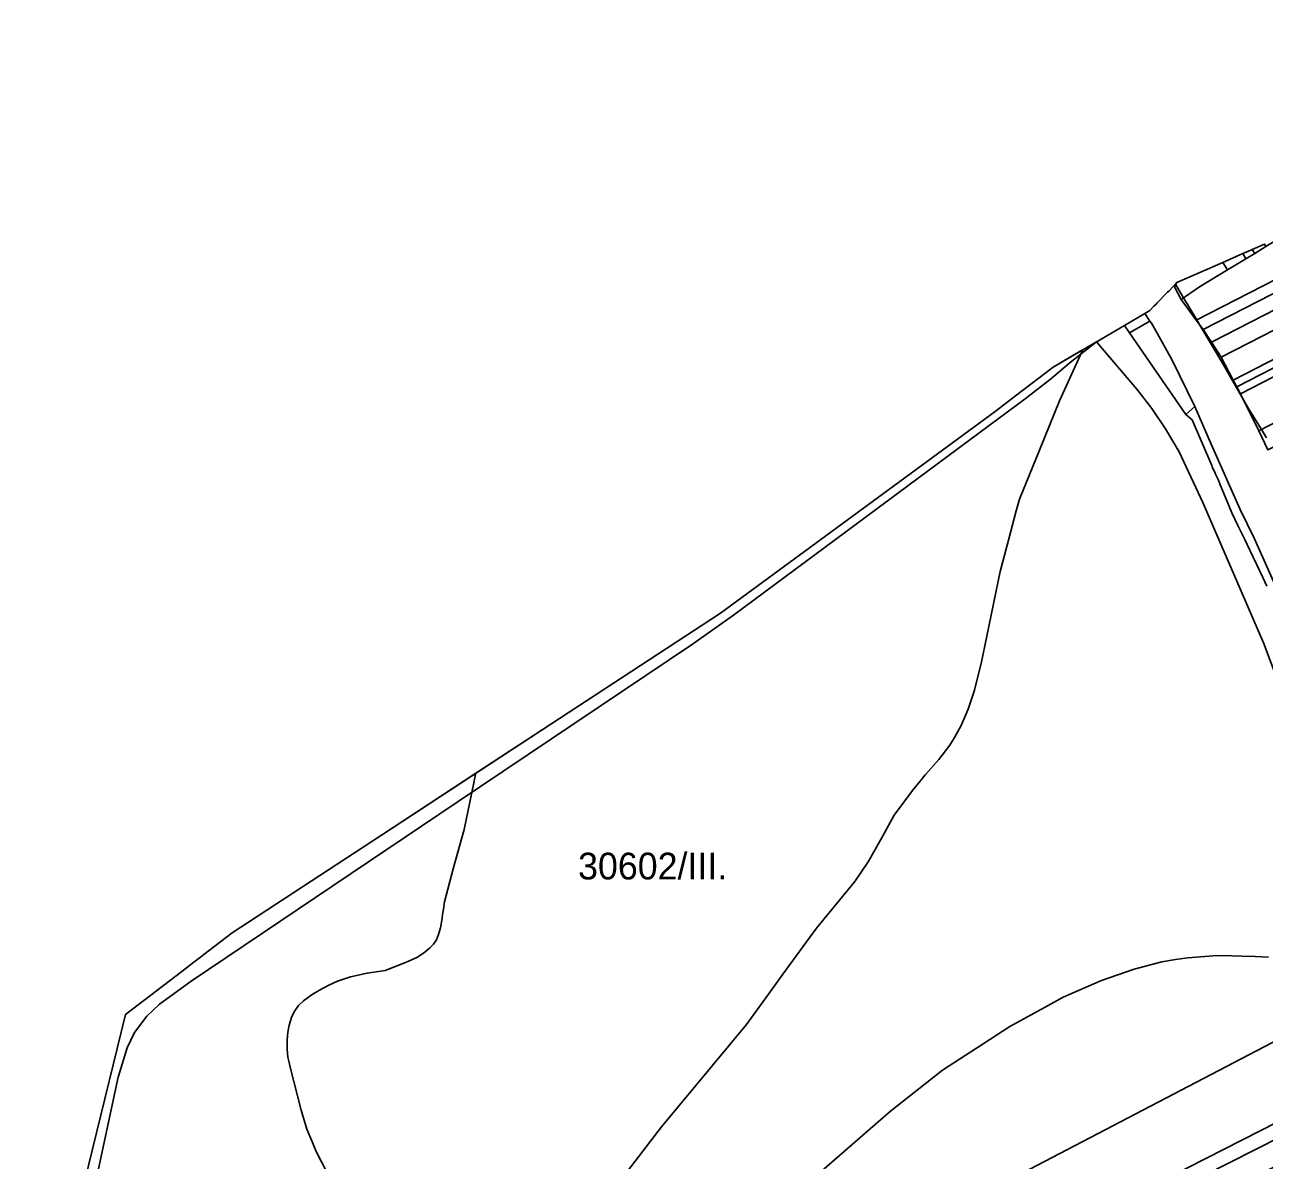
# Model space of a CAD drawing. Extents: x -521939 to -516426, y -1197857 to -1189551.
# Drawn here: x -521520 to -520825, y -1190213 to -1189576 of the extents above; entities that cross this region are included whole.
import ezdxf

# ---------------------------------------------------------------- set-up
doc = ezdxf.new("R2010")
doc.units = 0
for name, color, linetype in [('95560013', 7, 'Continuous'), ('95640013', 7, 'Continuous'), ('95660013', 7, 'Continuous')]:
    doc.layers.add(name, color=color, linetype=linetype)

msp = doc.modelspace()

# ---------------------------------------------------------------- linework, layer by layer
at = {"layer": '95560013'}
for points in [[(-520871.46, -1189729.85), (-520861.25, -1189722.78), (-520845.5, -1189713.21), (-520835.28, -1189707), (-520830.24, -1189703.94), (-520823.89, -1189700.08), (-520813.62, -1189693.84), (-520798.15, -1189685.87), (-520693.52, -1189631.98), (-520584.33, -1189575.74), (-520574.91, -1189593.69), (-520698.86, -1189657.27), (-520862.97, -1189741.45)], [(-520574.91, -1189593.69), (-520571.87, -1189599.49), (-520698.91, -1189664.62), (-520859.09, -1189746.74), (-520862.97, -1189741.45), (-520698.86, -1189657.27)], [(-520571.87, -1189599.49), (-520567.98, -1189606.88), (-520692.96, -1189670.96), (-520854.49, -1189753.78), (-520859.09, -1189746.74), (-520698.91, -1189664.62)], [(-520567.98, -1189606.88), (-520563.29, -1189615.69), (-520689.07, -1189680.22), (-520848.98, -1189762.26), (-520854.49, -1189753.78), (-520692.96, -1189670.96)], [(-520563.29, -1189615.69), (-520556.78, -1189628.12), (-520695.46, -1189699.52), (-520842.22, -1189775.08), (-520848.98, -1189762.26), (-520689.07, -1189680.22)], [(-520556.78, -1189628.12), (-520554.77, -1189631.94), (-520679.88, -1189696.34), (-520840.25, -1189778.89), (-520842.22, -1189775.08), (-520695.46, -1189699.52)], [(-520554.77, -1189631.94), (-520552.78, -1189635.77), (-520677.43, -1189699.92), (-520838.28, -1189782.7), (-520840.25, -1189778.89), (-520679.88, -1189696.34)], [(-520552.78, -1189635.77), (-520542.06, -1189656.2), (-520665.51, -1189719.78), (-520827.89, -1189803.41), (-520838.28, -1189782.7), (-520677.43, -1189699.92)], [(-520542.06, -1189656.2), (-520536.5, -1189666.75), (-520663.27, -1189732.03), (-520822.82, -1189814.19), (-520827.89, -1189803.41), (-520665.51, -1189719.78)], [(-520830.24, -1189703.94), (-520831.59, -1189701.76), (-520824.7, -1189698.73), (-520823.89, -1189700.08)], [(-520845.5, -1189713.21), (-520848.1, -1189709.03), (-520836.95, -1189704.12), (-520835.28, -1189707)], [(-520835.28, -1189707), (-520836.95, -1189704.12), (-520832.44, -1189702.13), (-520831.59, -1189701.76), (-520830.24, -1189703.94)], [(-520891.87, -1189737.62), (-520889, -1189741.91), (-520900.54, -1189748.5), (-520903.31, -1189744.33)], [(-520888.2, -1189743.1), (-520884.99, -1189748.66), (-520876.58, -1189763.88), (-520863.78, -1189789.93), (-520868.84, -1189794.27), (-520900.54, -1189748.5), (-520889, -1189741.91)], [(-521143.74, -1190315.4), (-520777.95, -1190124.57), (-520777.29, -1190138.74), (-520776.47, -1190163.36), (-520776.83, -1190170.44), (-521129.32, -1190350.03), (-521136.18, -1190333.63), (-521138.91, -1190327.09), (-521141.12, -1190321.7)], [(-521125.92, -1190356.73), (-521201.05, -1190394.9), (-521360.62, -1190475.97), (-521520.19, -1190557.04), (-521519.05, -1190548.23), (-521358.95, -1190466.81), (-521197.1, -1190384.5), (-521129.32, -1190350.03), (-520776.83, -1190170.44), (-520777.49, -1190180.07), (-520800.29, -1190191.63), (-520962.75, -1190274)], [(-521125.92, -1190356.73), (-520962.75, -1190274), (-520800.29, -1190191.63), (-520777.49, -1190180.07), (-520778.53, -1190195.44), (-520799.56, -1190206.22), (-520959.86, -1190288.39), (-521120.16, -1190370.56), (-521122.27, -1190365.51)]]:
    msp.add_lwpolyline(points, close=True, dxfattribs=at)
for points in [[(-521480.04, -1190222.68), (-521467.81, -1190165.95), (-521462.67, -1190149.67), (-521458.62, -1190141.01), (-521451.74, -1190131.75), (-521444.63, -1190125.14), (-521426.94, -1190112.16), (-521277.58, -1190011.81), (-521145.53, -1189923.09), (-521122.58, -1189906.88), (-520979.19, -1189800.51), (-520959.01, -1189785.54), (-520944.79, -1189774.51), (-520933.78, -1189765.22), (-520918.93, -1189753.5), (-520896.35, -1189780.16), (-520887.88, -1189790.95), (-520880.21, -1189802.32), (-520872.55, -1189815.19), (-520859.28, -1189843.65), (-520825.3, -1189922.44), (-520803.36, -1189980.65)], [(-520777.95, -1190124.57), (-521143.74, -1190315.4)]]:
    msp.add_lwpolyline(points, dxfattribs=at)
at = {"layer": '95640013'}
msp.add_lwpolyline([(-520875.18, -1189722.65), (-520873.85, -1189720.38), (-520848.1, -1189709.03), (-520845.5, -1189713.21), (-520861.25, -1189722.78), (-520871.46, -1189729.85)], close=True, dxfattribs=at)
for points in [[(-520813.42, -1189901.77), (-520830.43, -1189864.05), (-520838.34, -1189847.6), (-520854.68, -1189811.01), (-520863.78, -1189789.93), (-520876.58, -1189763.88), (-520884.99, -1189748.66), (-520888.2, -1189743.1), (-520889, -1189741.91), (-520891.87, -1189737.62), (-520889.06, -1189735.97), (-520886.75, -1189733.61), (-520885.77, -1189732.6), (-520884.86, -1189731.67), (-520879.1, -1189725.76), (-520878.47, -1189725.11), (-520878.3, -1189724.93), (-520873.85, -1189720.38), (-520875.18, -1189722.65), (-520871.46, -1189729.85), (-520862.97, -1189741.45), (-520859.09, -1189746.74), (-520854.49, -1189753.78), (-520848.98, -1189762.26), (-520842.22, -1189775.08), (-520840.25, -1189778.89), (-520838.28, -1189782.7), (-520827.89, -1189803.41), (-520822.82, -1189814.19)], [(-520803.36, -1189980.65), (-520825.3, -1189922.44), (-520859.28, -1189843.65), (-520872.55, -1189815.19), (-520880.21, -1189802.32), (-520887.88, -1189790.95), (-520896.35, -1189780.16), (-520918.93, -1189753.5), (-520918.65, -1189753.34), (-520903.31, -1189744.33), (-520900.54, -1189748.5), (-520868.84, -1189794.27), (-520865.38, -1189797.27), (-520854.32, -1189823.02), (-520854.03, -1189823.64), (-520852.36, -1189827.29), (-520852.17, -1189827.72), (-520850.55, -1189831.25), (-520849.51, -1189833.76), (-520846.54, -1189840.93), (-520843.01, -1189849.46), (-520839.61, -1189856.58), (-520835.85, -1189864.43), (-520832.97, -1189870.44), (-520829.04, -1189878.62), (-520825.65, -1189885.69), (-520823.49, -1189890.54)], [(-521489.18, -1190234.62), (-521463.67, -1190130.83), (-521432.08, -1190106.71), (-521425.29, -1190101.52), (-521421.67, -1190098.76), (-521419.72, -1190097.27), (-521403.82, -1190085.13), (-521320.06, -1190030.25), (-521225, -1189967.98), (-521129.95, -1189905.7), (-520975.8, -1189792.72), (-520964.34, -1189783.94), (-520943.19, -1189767.73), (-520918.93, -1189753.5), (-520933.78, -1189765.22), (-520944.79, -1189774.51), (-520959.01, -1189785.54), (-520979.19, -1189800.51), (-521122.58, -1189906.88), (-521145.53, -1189923.09), (-521277.58, -1190011.81), (-521426.94, -1190112.16), (-521444.63, -1190125.14), (-521451.74, -1190131.75), (-521458.62, -1190141.01), (-521462.67, -1190149.67), (-521467.81, -1190165.95), (-521480.04, -1190222.68)], [(-520823.49, -1189890.54), (-520825.65, -1189885.69), (-520829.04, -1189878.62), (-520832.97, -1189870.44), (-520835.85, -1189864.43), (-520839.61, -1189856.58), (-520843.01, -1189849.46), (-520846.54, -1189840.93), (-520849.51, -1189833.76), (-520850.55, -1189831.25), (-520852.17, -1189827.72), (-520852.36, -1189827.29), (-520854.03, -1189823.64), (-520854.32, -1189823.02), (-520865.38, -1189797.27), (-520868.84, -1189794.27), (-520863.78, -1189789.93), (-520854.68, -1189811.01), (-520838.34, -1189847.6), (-520830.43, -1189864.05), (-520813.42, -1189901.77)]]:
    msp.add_lwpolyline(points, dxfattribs=at)
at = {"layer": '95660013'}
for points in [[(-520823.56, -1189807.36), (-520826.49, -1189802.69), (-520830.43, -1189796.42), (-520833.59, -1189791.38), (-520836.57, -1189786.11), (-520847.7, -1189766.42), (-520860.96, -1189744.19), (-520862.68, -1189741.3), (-520870.08, -1189728.9), (-520873.84, -1189722.6), (-520874.5, -1189721.5), (-520874.67, -1189721.22), (-520873.85, -1189720.38), (-520848.1, -1189709.03), (-520836.95, -1189704.12), (-520832.44, -1189702.13), (-520831.59, -1189701.76), (-520824.7, -1189698.73)], [(-521239.8, -1190294.2), (-521163.05, -1190193.89), (-521115.23, -1190136.51), (-521100.61, -1190116.17), (-521094.94, -1190108.28), (-521076.04, -1190082.38), (-521054.58, -1190056.26), (-521047.11, -1190045.29), (-521039.88, -1190032.7), (-521032.42, -1190019.17), (-521022.15, -1190005.17), (-521017.91, -1190000), (-521015.05, -1189996.51), (-521014.69, -1189996.07), (-521007.46, -1189987.91), (-521001.16, -1189979.74), (-520998.64, -1189975.56), (-520994.9, -1189968.79), (-520993.2, -1189964.89), (-520990.94, -1189959.69), (-520987.44, -1189948.96), (-520983.47, -1189933.1), (-520981.64, -1189924.13), (-520973.09, -1189882.36), (-520968.43, -1189864.87), (-520964.11, -1189848.42), (-520962.24, -1189841.77), (-520950.93, -1189814.36), (-520939.73, -1189786.72), (-520928.11, -1189761.16), (-520927.82, -1189760.51), (-520926.7, -1189758.06), (-520928.1, -1189758.88), (-520943.19, -1189767.73), (-520918.93, -1189753.5), (-520918.65, -1189753.34), (-520903.31, -1189744.33), (-520891.87, -1189737.62), (-520889.06, -1189735.97), (-520886.75, -1189733.61), (-520885.77, -1189732.6), (-520884.86, -1189731.67), (-520879.1, -1189725.76), (-520878.47, -1189725.11), (-520878.3, -1189724.93), (-520873.85, -1189720.38), (-520874.67, -1189721.22), (-520874.5, -1189721.5), (-520873.84, -1189722.6), (-520870.08, -1189728.9), (-520862.68, -1189741.3), (-520860.96, -1189744.19), (-520847.7, -1189766.42), (-520836.57, -1189786.11), (-520833.59, -1189791.38), (-520830.43, -1189796.42), (-520826.49, -1189802.69), (-520823.56, -1189807.36)], [(-521350.73, -1190219.4), (-521356.72, -1190207.83), (-521358.88, -1190202.7), (-521362.05, -1190195.16), (-521365.17, -1190184.51), (-521371.25, -1190160.35), (-521372.06, -1190157.09), (-521372.61, -1190154.86), (-521373.03, -1190150.55), (-521372.94, -1190145.14), (-521372.79, -1190143.1), (-521372.61, -1190140.75), (-521371.85, -1190136.78), (-521370.58, -1190132.56), (-521369.14, -1190129.35), (-521366.61, -1190125.8), (-521363.82, -1190123.18), (-521359, -1190119.72), (-521354.95, -1190117.18), (-521349.54, -1190114.48), (-521344.81, -1190112.28), (-521337.55, -1190109.75), (-521328.09, -1190107.72), (-521317.95, -1190106.2), (-521307.47, -1190102.15), (-521304.02, -1190100.62), (-521300.21, -1190098.93), (-521296.49, -1190096.57), (-521293.11, -1190093.7), (-521290.91, -1190091.5), (-521289.22, -1190088.97), (-521288.04, -1190085.93), (-521287.03, -1190082.21), (-521286.18, -1190077.98), (-521285.59, -1190073.59), (-521285.34, -1190071.73), (-521284.83, -1190067.68), (-521279.93, -1190049.09), (-521273.68, -1190027.13), (-521269.37, -1190006.3), (-521268.07, -1190000), (-521267.85, -1189998.95), (-521267.16, -1189995.6), (-521225, -1189967.98), (-521129.95, -1189905.7), (-520975.8, -1189792.72), (-520964.34, -1189783.94), (-520943.19, -1189767.73), (-520928.1, -1189758.88), (-520926.7, -1189758.06), (-520927.82, -1189760.51), (-520928.11, -1189761.16), (-520939.73, -1189786.72), (-520950.93, -1189814.36), (-520962.24, -1189841.77), (-520964.11, -1189848.42), (-520968.43, -1189864.87), (-520973.09, -1189882.36), (-520981.64, -1189924.13), (-520983.47, -1189933.1), (-520987.44, -1189948.96), (-520990.94, -1189959.69), (-520993.2, -1189964.89), (-520994.9, -1189968.79), (-520998.64, -1189975.56), (-521001.16, -1189979.74), (-521007.46, -1189987.91), (-521014.69, -1189996.07), (-521015.05, -1189996.51), (-521017.91, -1190000), (-521022.15, -1190005.17), (-521032.42, -1190019.17), (-521039.88, -1190032.7), (-521047.11, -1190045.29), (-521054.58, -1190056.26), (-521076.04, -1190082.38), (-521094.94, -1190108.28), (-521100.61, -1190116.17), (-521115.23, -1190136.51), (-521163.05, -1190193.89), (-521239.8, -1190294.2)], [(-521320.06, -1190030.25), (-521267.16, -1189995.6), (-521267.85, -1189998.95), (-521268.07, -1190000), (-521269.37, -1190006.3), (-521273.68, -1190027.13), (-521279.93, -1190049.09), (-521284.83, -1190067.68), (-521285.34, -1190071.73), (-521285.59, -1190073.59), (-521286.18, -1190077.98), (-521287.03, -1190082.21), (-521288.04, -1190085.93), (-521289.22, -1190088.97), (-521290.91, -1190091.5), (-521293.11, -1190093.7), (-521296.49, -1190096.57), (-521300.21, -1190098.93), (-521304.02, -1190100.62), (-521307.47, -1190102.15), (-521317.95, -1190106.2), (-521328.09, -1190107.72), (-521337.55, -1190109.75), (-521344.81, -1190112.28), (-521349.54, -1190114.48), (-521354.95, -1190117.18), (-521359, -1190119.72), (-521363.82, -1190123.18), (-521366.61, -1190125.8), (-521369.14, -1190129.35), (-521370.58, -1190132.56), (-521371.85, -1190136.78), (-521372.61, -1190140.75), (-521372.79, -1190143.1), (-521372.94, -1190145.14), (-521373.03, -1190150.55), (-521372.61, -1190154.86), (-521372.06, -1190157.09), (-521371.25, -1190160.35), (-521365.17, -1190184.51), (-521362.05, -1190195.16), (-521358.88, -1190202.7), (-521356.72, -1190207.83), (-521350.73, -1190219.4)], [(-521489.18, -1190234.62), (-521463.67, -1190130.83), (-521432.08, -1190106.71), (-521425.29, -1190101.52), (-521421.67, -1190098.76), (-521419.72, -1190097.27), (-521403.82, -1190085.13), (-521320.06, -1190030.25)], [(-520822.42, -1190098.78), (-520830.02, -1190098.43), (-520837.45, -1190098.08), (-520842.92, -1190097.98), (-520851.06, -1190097.84), (-520867.73, -1190099.02), (-520874.6, -1190100.12), (-520882.28, -1190101.36), (-520897.84, -1190105.47), (-520916.15, -1190111.81), (-520937.74, -1190121.2), (-520946.16, -1190125.84), (-520967.56, -1190137.63), (-520986.33, -1190149.76), (-521005.35, -1190162.05), (-521034.46, -1190185.05), (-521063.1, -1190209.93), (-521088.69, -1190232.24)], [(-521088.69, -1190232.24), (-521063.1, -1190209.93), (-521034.46, -1190185.05), (-521005.35, -1190162.05), (-520986.33, -1190149.76), (-520967.56, -1190137.63), (-520946.16, -1190125.84), (-520937.74, -1190121.2), (-520916.15, -1190111.81), (-520897.84, -1190105.47), (-520882.28, -1190101.36), (-520874.6, -1190100.12), (-520867.73, -1190099.02), (-520851.06, -1190097.84), (-520842.92, -1190097.98), (-520837.45, -1190098.08), (-520830.02, -1190098.43), (-520822.42, -1190098.78)]]:
    msp.add_lwpolyline(points, dxfattribs=at)

# ---------------------------------------------------------------- texts
msp.add_text('30602/III.', height=15, rotation=360, dxfattribs=at).set_placement((-521209.79, -1190055.13))

doc.saveas('drawing.dxf')
